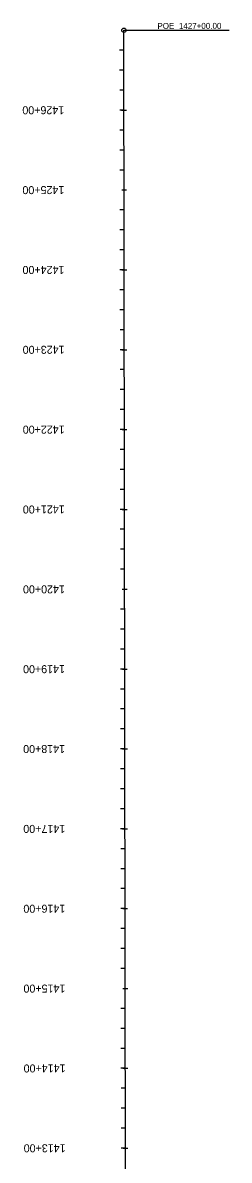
# Model space of a CAD drawing. Extents: x 14541681 to 14544384, y 8572153 to 8583558.
# Drawn here: x 14541681 to 14541939, y 8582134 to 8583558 of the extents above; entities that cross this region are included whole.
import ezdxf

# ---------------------------------------------------------------- set-up
doc = ezdxf.new("R2010")
doc.units = 0
for name, color, linetype in [('Alignment', 7, 'Continuous'), ('TextAlignment', 7, 'Continuous'), ('TextAlignmentLrg', 7, 'Continuous'), ('TextAlignmentSml', 7, 'Continuous')]:
    doc.layers.add(name, color=color, linetype=linetype)

msp = doc.modelspace()

# ---------------------------------------------------------------- linework, layer by layer
at = {"layer": 'Alignment'}
msp.add_line((14541811.5, 8580543.1), (14541807.4, 8583548.8), dxfattribs=at)
at = {"layer": 'TextAlignment'}
for p in [(14541807.4, 8583548.8), (14541939.4, 8583549)]:
    msp.add_line(p, (14541939.4, 8583549), dxfattribs=at)
msp.add_circle((14541807.4, 8583548.8), 2.67, dxfattribs=at)
at = {"layer": 'TextAlignmentLrg'}
for p, q in [((14541807.6, 8583448.8), (14541802.1, 8583448.8)), ((14541804.6, 8583348.8), (14541810.8, 8583348.8)), ((14541807.8, 8583248.8), (14541802.4, 8583248.8)), ((14541808, 8583148.8), (14541802.5, 8583148.8)), ((14541808.1, 8583048.8), (14541802.6, 8583048.8)), ((14541808.2, 8582948.8), (14541802.8, 8582948.8)), ((14541805.3, 8582848.8), (14541811.4, 8582848.8)), ((14541808.5, 8582748.8), (14541803.1, 8582748.8)), ((14541808.6, 8582648.8), (14541803.2, 8582648.8)), ((14541808.8, 8582548.8), (14541803.3, 8582548.8)), ((14541808.9, 8582448.8), (14541803.5, 8582448.8)), ((14541806, 8582348.8), (14541812.1, 8582348.8)), ((14541809.2, 8582248.8), (14541803.7, 8582248.8)), ((14541809.3, 8582148.8), (14541803.9, 8582148.8))]:
    msp.add_line(p, q, dxfattribs=at)
at = {"layer": 'TextAlignmentSml'}
for p, q in [((14541807.5, 8583523.8), (14541802, 8583523.8)), ((14541807.5, 8583498.8), (14541802, 8583498.8)), ((14541807.5, 8583473.8), (14541802.1, 8583473.8)), ((14541804.5, 8583448.8), (14541810.6, 8583448.8)), ((14541807.6, 8583423.8), (14541802.1, 8583423.8)), ((14541807.6, 8583398.8), (14541802.2, 8583398.8)), ((14541807.7, 8583373.8), (14541802.2, 8583373.8)), ((14541804.6, 8583348.8), (14541810.8, 8583348.8)), ((14541807.7, 8583323.8), (14541802.3, 8583323.8)), ((14541807.8, 8583298.8), (14541802.3, 8583298.8)), ((14541807.8, 8583273.8), (14541802.3, 8583273.8)), ((14541804.8, 8583248.8), (14541810.9, 8583248.8)), ((14541807.9, 8583223.8), (14541802.4, 8583223.8)), ((14541807.9, 8583198.8), (14541802.4, 8583198.8)), ((14541807.9, 8583173.8), (14541802.5, 8583173.8)), ((14541804.9, 8583148.8), (14541811, 8583148.8)), ((14541808, 8583123.8), (14541802.5, 8583123.8)), ((14541808, 8583098.8), (14541802.6, 8583098.8)), ((14541808.1, 8583073.8), (14541802.6, 8583073.8)), ((14541805, 8583048.8), (14541811.2, 8583048.8)), ((14541808.1, 8583023.8), (14541802.7, 8583023.8)), ((14541808.2, 8582998.8), (14541802.7, 8582998.8)), ((14541808.2, 8582973.8), (14541802.8, 8582973.8)), ((14541805.2, 8582948.8), (14541811.3, 8582948.8)), ((14541808.3, 8582923.8), (14541802.8, 8582923.8)), ((14541808.3, 8582898.8), (14541802.9, 8582898.8)), ((14541808.3, 8582873.8), (14541802.9, 8582873.8)), ((14541805.3, 8582848.8), (14541811.4, 8582848.8)), ((14541808.4, 8582823.8), (14541803, 8582823.8)), ((14541808.4, 8582798.8), (14541803, 8582798.8)), ((14541808.5, 8582773.8), (14541803, 8582773.8)), ((14541805.5, 8582748.8), (14541811.6, 8582748.8)), ((14541808.5, 8582723.8), (14541803.1, 8582723.8)), ((14541808.6, 8582698.8), (14541803.1, 8582698.8)), ((14541808.6, 8582673.8), (14541803.2, 8582673.8)), ((14541805.6, 8582648.8), (14541811.7, 8582648.8)), ((14541808.7, 8582623.8), (14541803.2, 8582623.8)), ((14541808.7, 8582598.8), (14541803.3, 8582598.8)), ((14541808.7, 8582573.8), (14541803.3, 8582573.8)), ((14541805.7, 8582548.8), (14541811.8, 8582548.8)), ((14541808.8, 8582523.8), (14541803.4, 8582523.8)), ((14541808.8, 8582498.8), (14541803.4, 8582498.8)), ((14541808.9, 8582473.8), (14541803.4, 8582473.8)), ((14541805.9, 8582448.8), (14541812, 8582448.8)), ((14541809, 8582423.8), (14541803.5, 8582423.8)), ((14541809, 8582398.8), (14541803.5, 8582398.8)), ((14541809, 8582373.8), (14541803.6, 8582373.8)), ((14541806, 8582348.8), (14541812.1, 8582348.8)), ((14541809.1, 8582323.8), (14541803.6, 8582323.8)), ((14541809.1, 8582298.8), (14541803.7, 8582298.8)), ((14541809.2, 8582273.8), (14541803.7, 8582273.8)), ((14541806.1, 8582248.8), (14541812.2, 8582248.8)), ((14541809.2, 8582223.8), (14541803.8, 8582223.8)), ((14541809.3, 8582198.8), (14541803.8, 8582198.8)), ((14541809.3, 8582173.8), (14541803.8, 8582173.8)), ((14541806.3, 8582148.8), (14541812.4, 8582148.8))]:
    msp.add_line(p, q, dxfattribs=at)

# ---------------------------------------------------------------- texts
at = {"layer": 'TextAlignment'}
for s, p in [('POE ', (14541849.4, 8583550.5)), ('1427+00.00', (14541876.3, 8583550.5))]:
    msp.add_text(s, height=7.5, rotation=0.077, dxfattribs=at).set_placement(p)
at = {"layer": 'TextAlignmentLrg'}
for s, p in [('1425+00', (14541732.7, 8583353.7)), ('1420+00', (14541733.4, 8582853.7)), ('1415+00', (14541734, 8582353.7))]:
    msp.add_text(s, height=10.02, rotation=180.077, dxfattribs=at).set_placement(p)
at = {"layer": 'TextAlignmentSml'}
for s, p in [('1426+00', (14541732.6, 8583453.7)), ('1425+00', (14541732.7, 8583353.7)), ('1424+00', (14541732.8, 8583253.7)), ('1423+00', (14541733, 8583153.7)), ('1422+00', (14541733.1, 8583053.7)), ('1421+00', (14541733.2, 8582953.7)), ('1420+00', (14541733.4, 8582853.7)), ('1419+00', (14541733.5, 8582753.7)), ('1418+00', (14541733.6, 8582653.7)), ('1417+00', (14541733.8, 8582553.7)), ('1416+00', (14541733.9, 8582453.7)), ('1415+00', (14541734, 8582353.7)), ('1414+00', (14541734.2, 8582253.7)), ('1413+00', (14541734.3, 8582153.7))]:
    msp.add_text(s, height=10.02, rotation=180.077, dxfattribs=at).set_placement(p)

doc.saveas('drawing.dxf')
